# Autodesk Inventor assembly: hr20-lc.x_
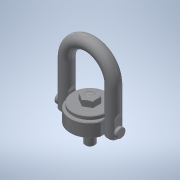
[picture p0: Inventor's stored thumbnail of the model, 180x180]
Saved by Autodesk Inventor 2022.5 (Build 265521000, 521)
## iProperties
Part Number: hr20-lc.x_
Material: 一般
Document SubType Name: Assembly
Designer: ImaoCorp
Sending System: SOLIDWORKS 2017-2017317
MC: AMD64
MC_MODEL: Intel64 Family 6 Model 60 Stepping 3, GenuineIntel
OS: Windows_NT
FRU: Parasolid Version 29.0, build 201,  4-17-2017
FORMAT: text
GUISE: transmit
KEY: hr20-lc
FILE: hr20-lc.x_t
DATE: Mon Jul 01 17:37:42 2019
Author: ImaoCorp
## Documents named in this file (3)
- X:\14_SW2022-Inv2022\00_全2023-1023新製品(TCC)まで\h\hr20-lc\HR20-LC.iam
- X:\14_SW2022-Inv2022\00_全2023-1023新製品(TCC)まで\h\hr20-lc\hr20-lc_01.ipt
- X:\14_SW2022-Inv2022\00_全2023-1023新製品(TCC)まで\h\hr20-lc\hr20-lc_02.ipt
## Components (2 placed, 2 different names)
1. hr20-lc_01
2. hr20-lc_02
